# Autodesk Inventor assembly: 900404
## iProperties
Created: 2007-10
Part Number: 900404
Document SubType Name: Assembly
Designer: TH
Mass: 84.5508 g
Surface Area: 361.459 cm^2
Volume: 32.7287 cm^3
Density: 2.58338 g/cm^3
Description: SERVO MOTOR 1000
Component Category: Electrical
Author: TH
